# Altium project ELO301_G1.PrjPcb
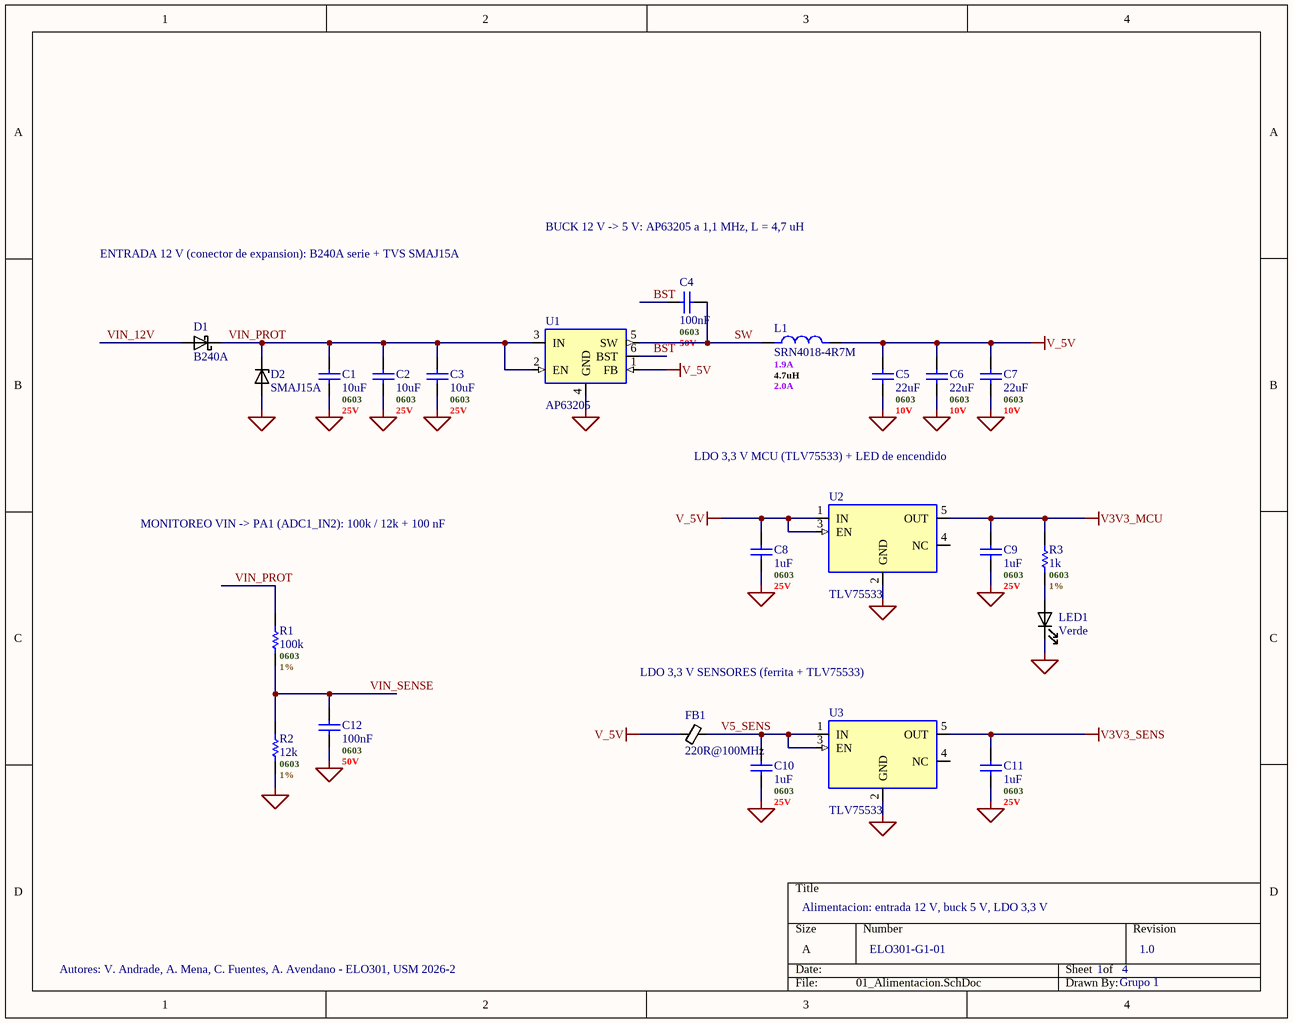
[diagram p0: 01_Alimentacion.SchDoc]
4 sheets, 68 parts. Net scope: global (net labels, ports and power ports of the same name join across sheets).
Board file: ELO301_G1.PcbDoc
Sheets:
  01_Alimentacion.SchDoc
  02_MCU.SchDoc
  03_Sensores.SchDoc
  04_Conectores.SchDoc

## Sheet 01_Alimentacion.SchDoc
size A; SheetNumber: 5; SheetTotal: 5

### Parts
C1  10uF  .Case/Package: 0603  .Voltage Rating (DC): 25V  [C0603 - MURATA]
C2  10uF  .Case/Package: 0603  .Voltage Rating (DC): 25V  [C0603 - MURATA]
C3  10uF  .Case/Package: 0603  .Voltage Rating (DC): 25V  [C0603 - MURATA]
C4  100nF  .Case/Package: 0603  .Voltage Rating (DC): 50V  [C0603 - MURATA]
C5  22uF  .Case/Package: 0603  .Voltage Rating (DC): 10V  [C0603 - MURATA]
C6  22uF  .Case/Package: 0603  .Voltage Rating (DC): 10V  [C0603 - MURATA]
C7  22uF  .Case/Package: 0603  .Voltage Rating (DC): 10V  [C0603 - MURATA]
C8  1uF  .Case/Package: 0603  .Voltage Rating (DC): 25V  [C0603 - MURATA]
C9  1uF  .Case/Package: 0603  .Voltage Rating (DC): 25V  [C0603 - MURATA]
C10  1uF  .Case/Package: 0603  .Voltage Rating (DC): 25V  [C0603 - MURATA]
C11  1uF  .Case/Package: 0603  .Voltage Rating (DC): 25V  [C0603 - MURATA]
C12  100nF  .Case/Package: 0603  .Voltage Rating (DC): 50V  [C0603 - MURATA]
D1  B240A  [SMA - DIODES]
D2  SMAJ15A  [SMA - DIODES]
FB1  220R@100MHz  [L0603 - GENERIC]
L1  SRN4018-4R7M  .RMS Current (Irms): 1.9A  .Value: 4.7uH  .Max DC Current: 2.0A  [SRN4018 - BOURNS]
LED1  Verde  [LED0603 - LITEON]
R1  100k  .Case/Package: 0603  .Tolerance: 1%  [R0603 - YAGEO]
R2  12k  .Case/Package: 0603  .Tolerance: 1%  [R0603 - YAGEO]
R3  1k  .Case/Package: 0603  .Tolerance: 1%  [R0603 - YAGEO]
U1  AP63205  [TSOT-23-6 - DIODES]
U2  TLV75533  [SOT-23-5 - TI]
U3  TLV75533  [SOT-23-5 - TI]

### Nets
GND: C1.2 C2.2 C3.2 C5.2 C6.2 C7.2 C8.2 C9.2 C10.2 C11.2 C12.2 D2.2(A) LED1.1(K) R2.1 U1.4(GND) U2.2(GND) U3.2(GND)
V3V3_MCU: C9.1 R3.2 U2.5(OUT)
V3V3_SENS: C11.1 U3.5(OUT)
V_5V: C5.1 C6.1 C7.1 C8.1 FB1.1 L1.2 U1.1(FB) U2.1(IN) U2.3(EN)
BST: C4.1 U1.6(BST)
SW: C4.2 L1.1 U1.5(SW)
V5_SENS: C10.1 FB1.2 U3.1(IN) U3.3(EN)
VIN_12V: D1.2(A)
VIN_PROT: C1.1 C2.1 C3.1 D1.1(K) D2.1(K) R1.2 U1.2(EN) U1.3(IN)
VIN_SENSE: C12.1 R1.1 R2.2
NetLED1_2: LED1.2(A) R3.1

Not connected (* = marked no-connect by the designer): U2 4(NC); U3 4(NC)

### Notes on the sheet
- BUCK 12 V -> 5 V: AP63205 a 1,1 MHz, L = 4,7 uH
- ENTRADA 12 V (conector de expansion): B240A serie + TVS SMAJ15A
- LDO 3,3 V MCU (TLV75533) + LED de encendido
- MONITOREO VIN -> PA1 (ADC1_IN2): 100k / 12k + 100 nF
- LDO 3,3 V SENSORES (ferrita + TLV75533)
- Alimentacion: entrada 12 V, buck 5 V, LDO 3,3 V
- Autores: V. Andrade, A. Mena, C. Fuentes, A. Avendano - ELO301, USM 2026-2
- ELO301-G1-01
- 1
- 4
- 1.0
- Grupo 1

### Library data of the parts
C1-C3 = CAP - GENERIC: Manufacturer: Murata; Manufacturer Part Number: GRM188R61E106MA73D
C4 C12 = CAP - GENERIC: Manufacturer: Murata; Manufacturer Part Number: GRM188R71H104KA93D
C5-C7 = CAP - GENERIC: Manufacturer: Murata; Manufacturer Part Number: GRM188R61A226ME15D
C8-C11 = CAP - GENERIC: Manufacturer: Murata; Manufacturer Part Number: GRM188R61E105KA12D
D1 = B240A-13-F: Schottky diode; Manufacturer: Diodes Inc.
D2 = SMAJ15A-13-F: Diodes SMAJ15A TVS unidireccional 400 W, 15 V de trabajo, SMA; Manufacturer: Diodes Inc.
FB1 = FERRITE - GENERIC: Ferrite bead, small symbol; Manufacturer: Murata; Manufacturer Part Number: BLM18PG221SN1D
L1 = INDUCTOR - GENERIC: Manufacturer: Bourns; Value: 4.7uH
LED1 = LED - GENERIC: Light emitting diode; Manufacturer: Lite-On; Manufacturer Part Number: LTST-C191KGKT
R1 = RESISTOR - GENERIC: Manufacturer: Yageo; Manufacturer Part Number: RC0603FR-07100KL
R2 = RESISTOR - GENERIC: Manufacturer: Yageo; Manufacturer Part Number: RC0603FR-0712KL
R3 = RESISTOR - GENERIC: Manufacturer: Yageo; Manufacturer Part Number: RC0603FR-071KL
U1 = AP63205WU-7: 2A, 1.1MHz Buck DC/DC Converter, fixed 5.0V output voltage, TSOT-23-6; Manufacturer: Diodes Inc.
U2 U3 = TLV75533PDBVR: TI TLV75533 LDO 500 mA, salida fija 3,3 V, SOT-23-5; Manufacturer: Texas Instruments

## Sheet 02_MCU.SchDoc
size A; SheetNumber: 5; SheetTotal: 5
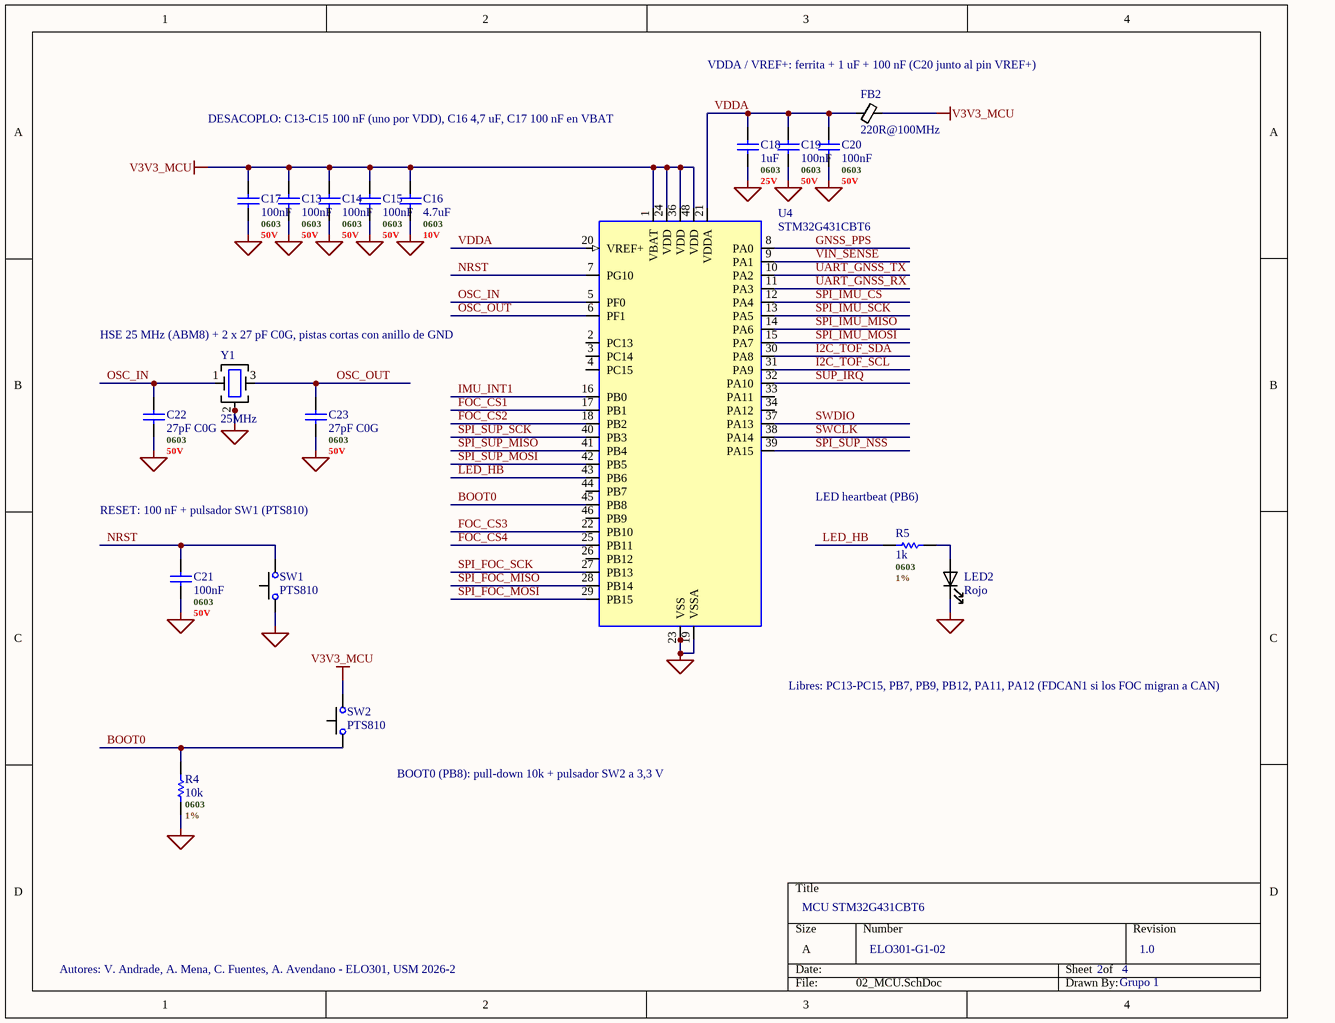
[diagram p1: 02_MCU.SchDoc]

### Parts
C13  100nF  .Case/Package: 0603  .Voltage Rating (DC): 50V  [C0603 - MURATA]
C14  100nF  .Case/Package: 0603  .Voltage Rating (DC): 50V  [C0603 - MURATA]
C15  100nF  .Case/Package: 0603  .Voltage Rating (DC): 50V  [C0603 - MURATA]
C16  4.7uF  .Case/Package: 0603  .Voltage Rating (DC): 10V  [C0603 - MURATA]
C17  100nF  .Case/Package: 0603  .Voltage Rating (DC): 50V  [C0603 - MURATA]
C18  1uF  .Case/Package: 0603  .Voltage Rating (DC): 25V  [C0603 - MURATA]
C19  100nF  .Case/Package: 0603  .Voltage Rating (DC): 50V  [C0603 - MURATA]
C20  100nF  .Case/Package: 0603  .Voltage Rating (DC): 50V  [C0603 - MURATA]
C21  100nF  .Case/Package: 0603  .Voltage Rating (DC): 50V  [C0603 - MURATA]
C22  27pF C0G  .Case/Package: 0603  .Voltage Rating (DC): 50V  [C0603 - MURATA]
C23  27pF C0G  .Case/Package: 0603  .Voltage Rating (DC): 50V  [C0603 - MURATA]
FB2  220R@100MHz  [L0603 - GENERIC]
LED2  Rojo  [LED0603 - LITEON]
R4  10k  .Case/Package: 0603  .Tolerance: 1%  [R0603 - YAGEO]
R5  1k  .Case/Package: 0603  .Tolerance: 1%  [R0603 - YAGEO]
SW1  PTS810  [PTS810 - CK]
SW2  PTS810  [PTS810 - CK]
U4  STM32G431CBT6  [LQFP-48 - ST]
Y1  25MHz  [ABM8 - ABRACON]

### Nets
GND: C13.2 C14.2 C15.2 C16.2 C17.2 C18.2 C19.2 C20.2 C21.2 C22.2 C23.2 LED2.1(K) R4.1 SW1.1 U4.19(VSSA) U4.23(VSS) U4.35(VSS) U4.47(VSS) Y1.2(G) Y1.4(G)
V3V3_MCU: C13.1 C14.1 C15.1 C16.1 C17.1 FB2.2 SW2.2 U4.1(VBAT) U4.24(VDD) U4.36(VDD) U4.48(VDD)
BOOT0: R4.2 SW2.1 U4.45(PB8)
FOC_CS1: U4.17(PB1)
FOC_CS2: U4.18(PB2)
FOC_CS3: U4.22(PB10)
FOC_CS4: U4.25(PB11)
GNSS_PPS: U4.8(PA0)
I2C_TOF_SCL: U4.31(PA9)
I2C_TOF_SDA: U4.30(PA8)
IMU_INT1: U4.16(PB0)
LED_HB: R5.1 U4.43(PB6)
NRST: C21.1 SW1.2 U4.7(PG10)
OSC_IN: C22.1 U4.5(PF0) Y1.1
OSC_OUT: C23.1 U4.6(PF1) Y1.3
SPI_FOC_MISO: U4.28(PB14)
SPI_FOC_MOSI: U4.29(PB15)
SPI_FOC_SCK: U4.27(PB13)
SPI_IMU_CS: U4.12(PA4)
SPI_IMU_MISO: U4.14(PA6)
SPI_IMU_MOSI: U4.15(PA7)
SPI_IMU_SCK: U4.13(PA5)
SPI_SUP_MISO: U4.41(PB4)
SPI_SUP_MOSI: U4.42(PB5)
SPI_SUP_NSS: U4.39(PA15)
SPI_SUP_SCK: U4.40(PB3)
SUP_IRQ: U4.32(PA10)
SWCLK: U4.38(PA14)
SWDIO: U4.37(PA13)
UART_GNSS_RX: U4.11(PA3)
UART_GNSS_TX: U4.10(PA2)
VDDA: C18.1 C19.1 C20.1 FB2.1 U4.20(VREF+) U4.21(VDDA)
VIN_SENSE: U4.9(PA1)
NetLED2_2: LED2.2(A) R5.2

Not connected (* = marked no-connect by the designer): U4 2(PC13) 3(PC14) 4(PC15) 26(PB12) 33(PA11) 34(PA12) 44(PB7) 46(PB9)

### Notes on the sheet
- (near FB2) VDDA / VREF+: ferrita + 1 uF + 100 nF (C20 junto al pin VREF+)
- DESACOPLO: C13-C15 100 nF (uno por VDD), C16 4,7 uF, C17 100 nF en VBAT
- (near Y1) HSE 25 MHz (ABM8) + 2 x 27 pF C0G, pistas cortas con anillo de GND
- LED heartbeat (PB6)
- RESET: 100 nF + pulsador SW1 (PTS810)
- Libres: PC13-PC15, PB7, PB9, PB12, PA11, PA12 (FDCAN1 si los FOC migran a CAN)
- BOOT0 (PB8): pull-down 10k + pulsador SW2 a 3,3 V
- MCU STM32G431CBT6
- Autores: V. Andrade, A. Mena, C. Fuentes, A. Avendano - ELO301, USM 2026-2
- ELO301-G1-02
- 2
- 4
- 1.0
- Grupo 1

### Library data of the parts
C13-C15 C17 C19-C21 = CAP - GENERIC: as C4 on sheet 01_Alimentacion
C16 = CAP - GENERIC: Manufacturer: Murata; Manufacturer Part Number: GRM188R61A475KE15D
C18 = CAP - GENERIC: as C8 on sheet 01_Alimentacion
C22 C23 = CAP - GENERIC: Manufacturer: Murata; Manufacturer Part Number: GRM1885C1H270JA01D
FB2 = FERRITE - GENERIC: as FB1 on sheet 01_Alimentacion
LED2 = LED - GENERIC: Light emitting diode; Manufacturer: Lite-On; Manufacturer Part Number: LTST-C191KRKT
R4 = RESISTOR - GENERIC: Manufacturer: Yageo; Manufacturer Part Number: RC0603FR-0710KL
R5 = RESISTOR - GENERIC: as R3 on sheet 01_Alimentacion
SW1 SW2 = PTS810 SJM 250 SMTR LFS: Push button switch, generic, two pins; Manufacturer: C&K
U4 = STM32G431CBT6: STMicroelectronics Arm Cortex-M4 MCU, 128KB flash, 32KB RAM, 170 MHz, 1.71-3.6V, 38 GPIO, LQFP48
Y1 = ABM8-25.000MHZ-B2-T: Four pin crystal, GND on pins 2 and 4; Manufacturer: Abracon

## Sheet 03_Sensores.SchDoc
size A; SheetNumber: 5; SheetTotal: 5
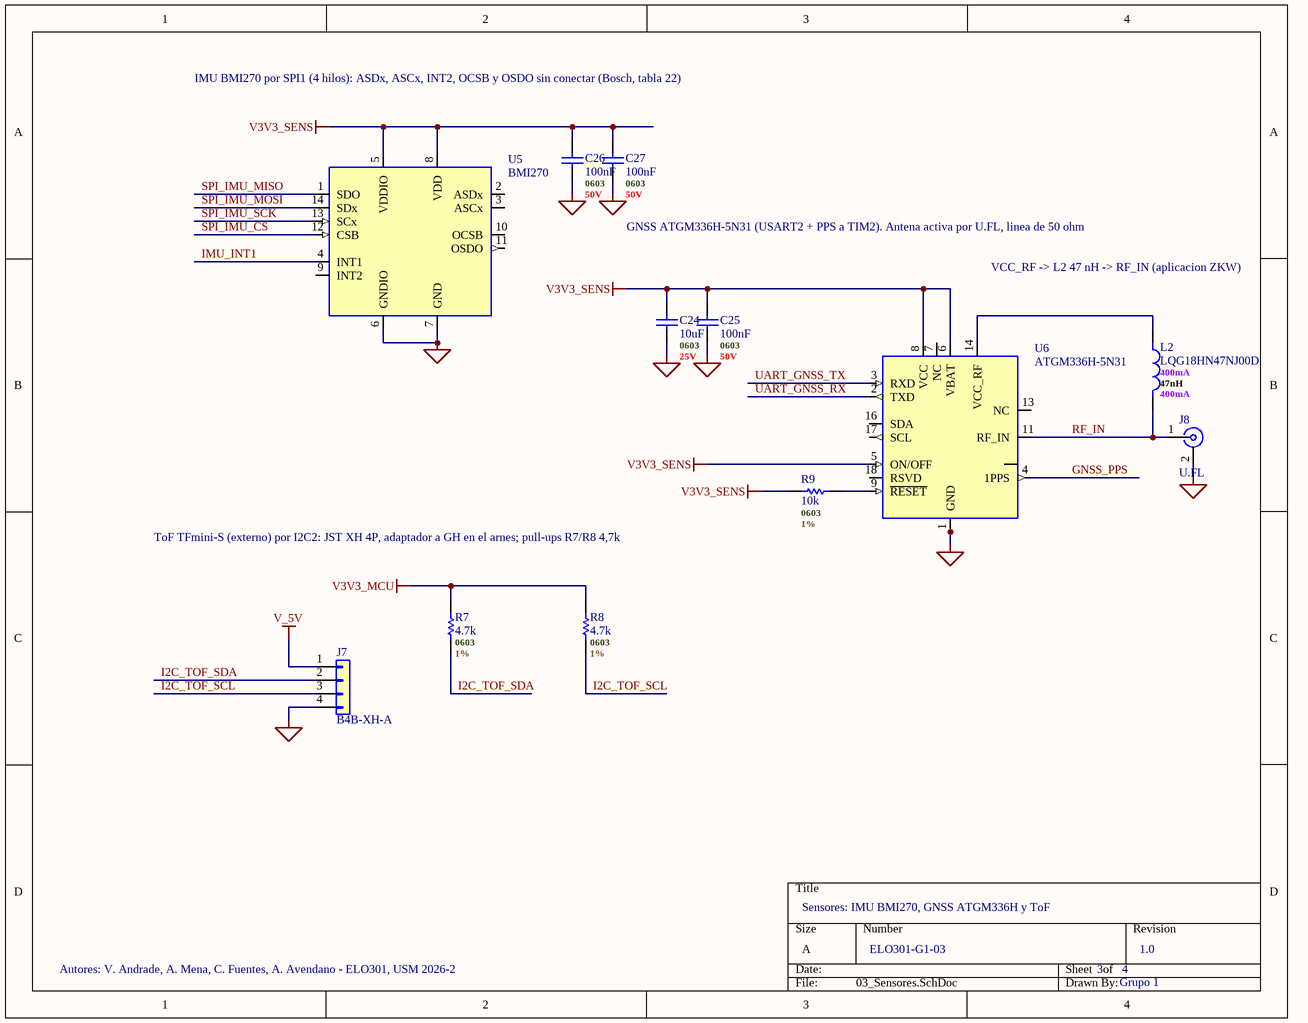
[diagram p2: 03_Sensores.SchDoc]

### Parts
C24  10uF  .Case/Package: 0603  .Voltage Rating (DC): 25V  [C0603 - MURATA]
C25  100nF  .Case/Package: 0603  .Voltage Rating (DC): 50V  [C0603 - MURATA]
C26  100nF  .Case/Package: 0603  .Voltage Rating (DC): 50V  [C0603 - MURATA]
C27  100nF  .Case/Package: 0603  .Voltage Rating (DC): 50V  [C0603 - MURATA]
J7  B4B-XH-A  [B4B-XH-A - JST]
J8  U.FL  [U.FL - HIROSE]
L2  LQG18HN47NJ00D  .RMS Current (Irms): 400mA  .Value: 47nH  [L0603 - GENERIC]
R7  4.7k  .Case/Package: 0603  .Tolerance: 1%  [R0603 - YAGEO]
R8  4.7k  .Case/Package: 0603  .Tolerance: 1%  [R0603 - YAGEO]
R9  10k  .Case/Package: 0603  .Tolerance: 1%  [R0603 - YAGEO]
U5  BMI270  [LGA-14 2.5x3.0 - BOSCH]
U6  ATGM336H-5N31  [LCC-18 9.7x10.1 - ZKW]

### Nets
GND: C24.2 C25.2 C26.2 C27.2 J7.4(Pin_4) J8.2(Ext) U5.6(GNDIO) U5.7(GND) U6.1(GND) U6.10(GND) U6.12(GND)
V3V3_MCU: R7.2 R8.2
V3V3_SENS: C24.1 C25.1 C26.1 C27.1 R9.1 U5.5(VDDIO) U5.8(VDD) U6.5(ON/OFF) U6.6(VBAT) U6.8(VCC)
V_5V: J7.1(Pin_1)
GNSS_PPS: U6.4(1PPS)
I2C_TOF_SCL: J7.3(Pin_3) R8.1
I2C_TOF_SDA: J7.2(Pin_2) R7.1
IMU_INT1: U5.4(INT1)
RF_IN: J8.1(In) L2.2 U6.11(RF_IN)
SPI_IMU_CS: U5.12(CSB)
SPI_IMU_MISO: U5.1(SDO)
SPI_IMU_MOSI: U5.14(SDx)
SPI_IMU_SCK: U5.13(SCx)
UART_GNSS_RX: U6.2(TXD)
UART_GNSS_TX: U6.3(RXD)
NetL2_1: L2.1 U6.14(VCC_RF)
NetR9_2: R9.2 U6.9(~{RESET})

Not connected (* = marked no-connect by the designer): U5 2(ASDx) 3(ASCx) 9(INT2) 10(OCSB) 11(OSDO); U6 7(NC) 13(NC) 15(RSVD) 16(SDA) 17(SCL) 18(RSVD)

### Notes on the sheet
- IMU BMI270 por SPI1 (4 hilos): ASDx, ASCx, INT2, OCSB y OSDO sin conectar (Bosch, tabla 22)
- GNSS ATGM336H-5N31 (USART2 + PPS a TIM2). Antena activa por U.FL, linea de 50 ohm
- VCC_RF -> L2 47 nH -> RF_IN (aplicacion ZKW)
- ToF TFmini-S (externo) por I2C2: JST XH 4P, adaptador a GH en el arnes; pull-ups R7/R8 4,7k
- Sensores: IMU BMI270, GNSS ATGM336H y ToF
- Autores: V. Andrade, A. Mena, C. Fuentes, A. Avendano - ELO301, USM 2026-2
- ELO301-G1-03
- 3
- 4
- 1.0
- Grupo 1

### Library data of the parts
C24 = CAP - GENERIC: as C1 on sheet 01_Alimentacion
C25-C27 = CAP - GENERIC: as C4 on sheet 01_Alimentacion
J7 = CONN - 1x04: Generic connector, single row, 01x04, script generated (kicad-library-utils/schlib/autogen/connector/); Manufacturer: JST; Manufacturer Part Number: B4B-XH-A(LF)(SN)
J8 = U.FL-R-SMT-1(10): coaxial connector (BNC, SMA, SMB, SMC, Cinch/RCA, LEMO, ...); Manufacturer: Hirose
L2 = INDUCTOR - GENERIC: Manufacturer: Murata; Value: 47nH
R7 R8 = RESISTOR - GENERIC: Manufacturer: Yageo; Manufacturer Part Number: RC0603FR-074K7L
R9 = RESISTOR - GENERIC: as R4 on sheet 02_MCU
U5 = BMI270: Bosch BMI270 IMU 6 ejes (acelerometro + giroscopio), SPI/I2C, LGA-14 2.5x3.0mm; Manufacturer: Bosch Sensortec
U6 = ATGM336H-5N31: ZKW ATGM336H-5N31 modulo GNSS GPS+BDS, UART + 1PPS, LCC-18 9.7x10.1mm (huella compatible u-blox MAX); Manufacturer: ZKW (Hangzhou ZhongKe)

## Sheet 04_Conectores.SchDoc
size A; SheetNumber: 5; SheetTotal: 5
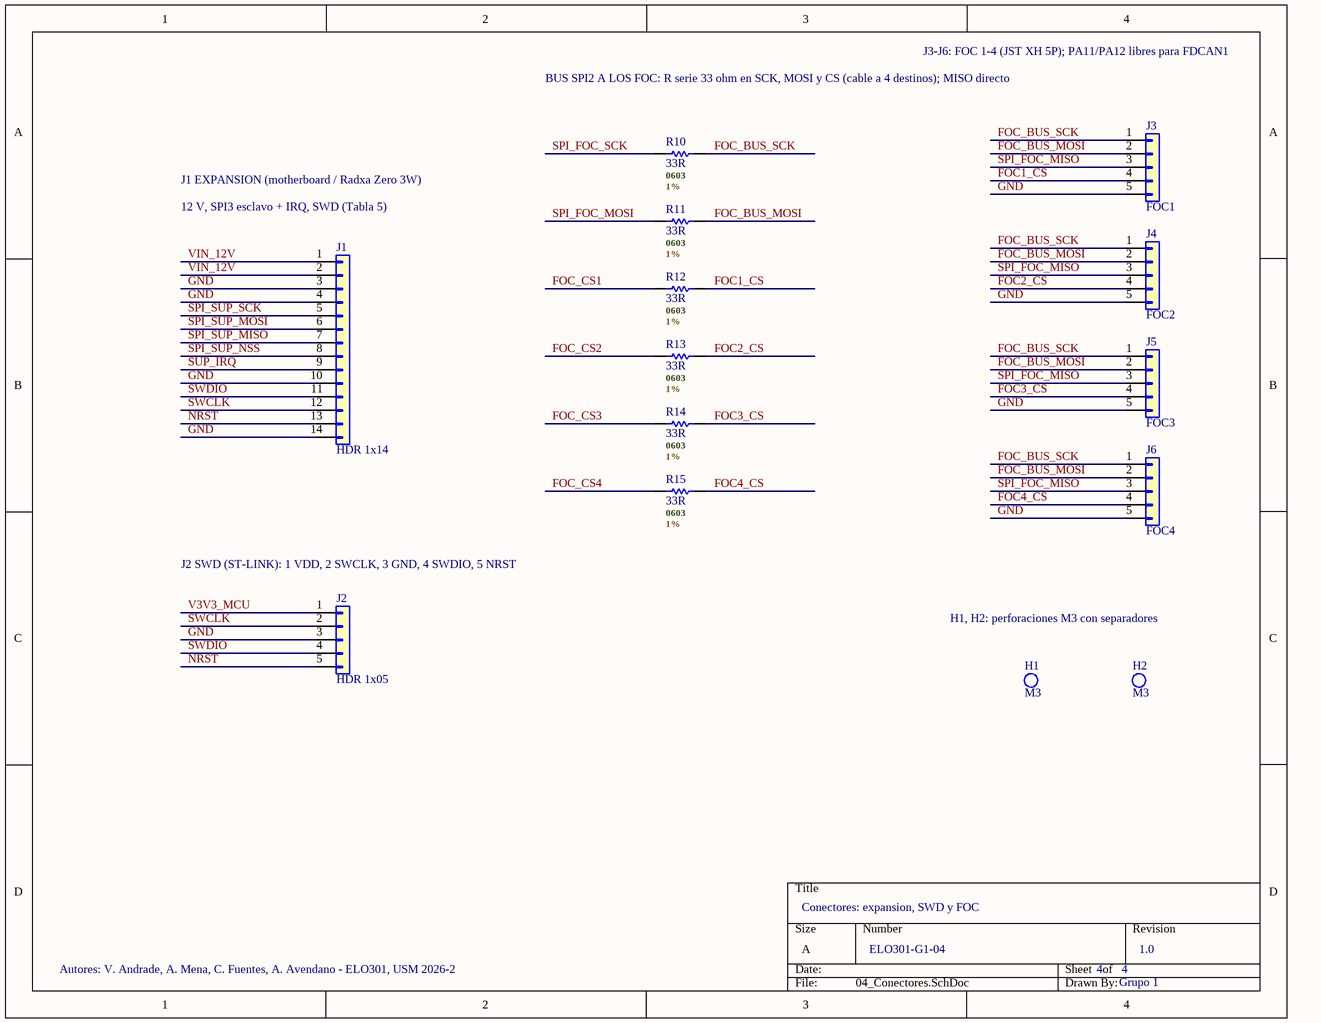
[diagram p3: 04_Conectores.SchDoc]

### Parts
H1  M3  [M3 - HOLE]
H2  M3  [M3 - HOLE]
J1  HDR 1x14  [HDR 1x14 2.54 - BOOMELE]
J2  HDR 1x05  [HDR 1x05 2.54 - BOOMELE]
J3  FOC1  [B5B-XH-A - JST]
J4  FOC2  [B5B-XH-A - JST]
J5  FOC3  [B5B-XH-A - JST]
J6  FOC4  [B5B-XH-A - JST]
R10  33R  .Case/Package: 0603  .Tolerance: 1%  [R0603 - YAGEO]
R11  33R  .Case/Package: 0603  .Tolerance: 1%  [R0603 - YAGEO]
R12  33R  .Case/Package: 0603  .Tolerance: 1%  [R0603 - YAGEO]
R13  33R  .Case/Package: 0603  .Tolerance: 1%  [R0603 - YAGEO]
R14  33R  .Case/Package: 0603  .Tolerance: 1%  [R0603 - YAGEO]
R15  33R  .Case/Package: 0603  .Tolerance: 1%  [R0603 - YAGEO]

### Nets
GND: J1.3(Pin_3) J1.4(Pin_4) J1.10(Pin_10) J1.14(Pin_14) J2.3(Pin_3) J3.5(Pin_5) J4.5(Pin_5) J5.5(Pin_5) J6.5(Pin_5)
V3V3_MCU: J2.1(Pin_1)
FOC1_CS: J3.4(Pin_4) R12.2
FOC2_CS: J4.4(Pin_4) R13.2
FOC3_CS: J5.4(Pin_4) R14.2
FOC4_CS: J6.4(Pin_4) R15.2
FOC_BUS_MOSI: J3.2(Pin_2) J4.2(Pin_2) J5.2(Pin_2) J6.2(Pin_2) R11.2
FOC_BUS_SCK: J3.1(Pin_1) J4.1(Pin_1) J5.1(Pin_1) J6.1(Pin_1) R10.2
FOC_CS1: R12.1
FOC_CS2: R13.1
FOC_CS3: R14.1
FOC_CS4: R15.1
NRST: J1.13(Pin_13) J2.5(Pin_5)
SPI_FOC_MISO: J3.3(Pin_3) J4.3(Pin_3) J5.3(Pin_3) J6.3(Pin_3)
SPI_FOC_MOSI: R11.1
SPI_FOC_SCK: R10.1
SPI_SUP_MISO: J1.7(Pin_7)
SPI_SUP_MOSI: J1.6(Pin_6)
SPI_SUP_NSS: J1.8(Pin_8)
SPI_SUP_SCK: J1.5(Pin_5)
SUP_IRQ: J1.9(Pin_9)
SWCLK: J1.12(Pin_12) J2.2(Pin_2)
SWDIO: J1.11(Pin_11) J2.4(Pin_4)
VIN_12V: J1.1(Pin_1) J1.2(Pin_2)

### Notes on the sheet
- BUS SPI2 A LOS FOC: R serie 33 ohm en SCK, MOSI y CS (cable a 4 destinos); MISO directo
- J3-J6: FOC 1-4 (JST XH 5P); PA11/PA12 libres para FDCAN1
- J1 EXPANSION (motherboard / Radxa Zero 3W)
- (near J1) 12 V, SPI3 esclavo + IRQ, SWD (Tabla 5)
- (near J2) J2 SWD (ST-LINK): 1 VDD, 2 SWCLK, 3 GND, 4 SWDIO, 5 NRST
- H1, H2: perforaciones M3 con separadores
- Conectores: expansion, SWD y FOC
- Autores: V. Andrade, A. Mena, C. Fuentes, A. Avendano - ELO301, USM 2026-2
- ELO301-G1-04
- 4
- 1.0
- Grupo 1

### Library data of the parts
H1 H2 = MOUNTING HOLE - M3: Mounting Hole without connection
J1 = CONN - 1x14: Generic connector, single row, 01x14, script generated (kicad-library-utils/schlib/autogen/connector/); Manufacturer: BOOMELE; Manufacturer Part Number: 2.54-1*40P (1x14)
J2 = CONN - 1x05: Generic connector, single row, 01x05, script generated (kicad-library-utils/schlib/autogen/connector/); Manufacturer: BOOMELE; Manufacturer Part Number: 2.54-1*40P (1x5)
J3-J6 = CONN - 1x05: Generic connector, single row, 01x05, script generated (kicad-library-utils/schlib/autogen/connector/); Manufacturer: JST; Manufacturer Part Number: B5B-XH-A(LF)(SN)
R10-R15 = RESISTOR - GENERIC: Manufacturer: Yageo; Manufacturer Part Number: RC0603FR-0733RL

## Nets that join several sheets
GND: 01_Alimentacion (17 pins), 02_MCU (20 pins), 03_Sensores (11 pins), 04_Conectores (9 pins)
V3V3_MCU: 01_Alimentacion (C9.1 R3.2 U2.5), 02_MCU (11 pins), 03_Sensores (R7.2 R8.2), 04_Conectores (J2.1)
V3V3_SENS: 01_Alimentacion (C11.1 U3.5), 03_Sensores (10 pins)
V_5V: 01_Alimentacion (9 pins), 03_Sensores (J7.1)
FOC_CS1: 02_MCU (U4.17), 04_Conectores (R12.1)
FOC_CS2: 02_MCU (U4.18), 04_Conectores (R13.1)
FOC_CS3: 02_MCU (U4.22), 04_Conectores (R14.1)
FOC_CS4: 02_MCU (U4.25), 04_Conectores (R15.1)
GNSS_PPS: 02_MCU (U4.8), 03_Sensores (U6.4)
I2C_TOF_SCL: 02_MCU (U4.31), 03_Sensores (J7.3 R8.1)
I2C_TOF_SDA: 02_MCU (U4.30), 03_Sensores (J7.2 R7.1)
IMU_INT1: 02_MCU (U4.16), 03_Sensores (U5.4)
NRST: 02_MCU (C21.1 SW1.2 U4.7), 04_Conectores (J1.13 J2.5)
SPI_FOC_MISO: 02_MCU (U4.28), 04_Conectores (J3.3 J4.3 J5.3 J6.3)
SPI_FOC_MOSI: 02_MCU (U4.29), 04_Conectores (R11.1)
SPI_FOC_SCK: 02_MCU (U4.27), 04_Conectores (R10.1)
SPI_IMU_CS: 02_MCU (U4.12), 03_Sensores (U5.12)
SPI_IMU_MISO: 02_MCU (U4.14), 03_Sensores (U5.1)
SPI_IMU_MOSI: 02_MCU (U4.15), 03_Sensores (U5.14)
SPI_IMU_SCK: 02_MCU (U4.13), 03_Sensores (U5.13)
SPI_SUP_MISO: 02_MCU (U4.41), 04_Conectores (J1.7)
SPI_SUP_MOSI: 02_MCU (U4.42), 04_Conectores (J1.6)
SPI_SUP_NSS: 02_MCU (U4.39), 04_Conectores (J1.8)
SPI_SUP_SCK: 02_MCU (U4.40), 04_Conectores (J1.5)
SUP_IRQ: 02_MCU (U4.32), 04_Conectores (J1.9)
SWCLK: 02_MCU (U4.38), 04_Conectores (J1.12 J2.2)
SWDIO: 02_MCU (U4.37), 04_Conectores (J1.11 J2.4)
UART_GNSS_RX: 02_MCU (U4.11), 03_Sensores (U6.2)
UART_GNSS_TX: 02_MCU (U4.10), 03_Sensores (U6.3)
VIN_12V: 01_Alimentacion (D1.2), 04_Conectores (J1.1 J1.2)
VIN_SENSE: 01_Alimentacion (C12.1 R1.1 R2.2), 02_MCU (U4.9)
